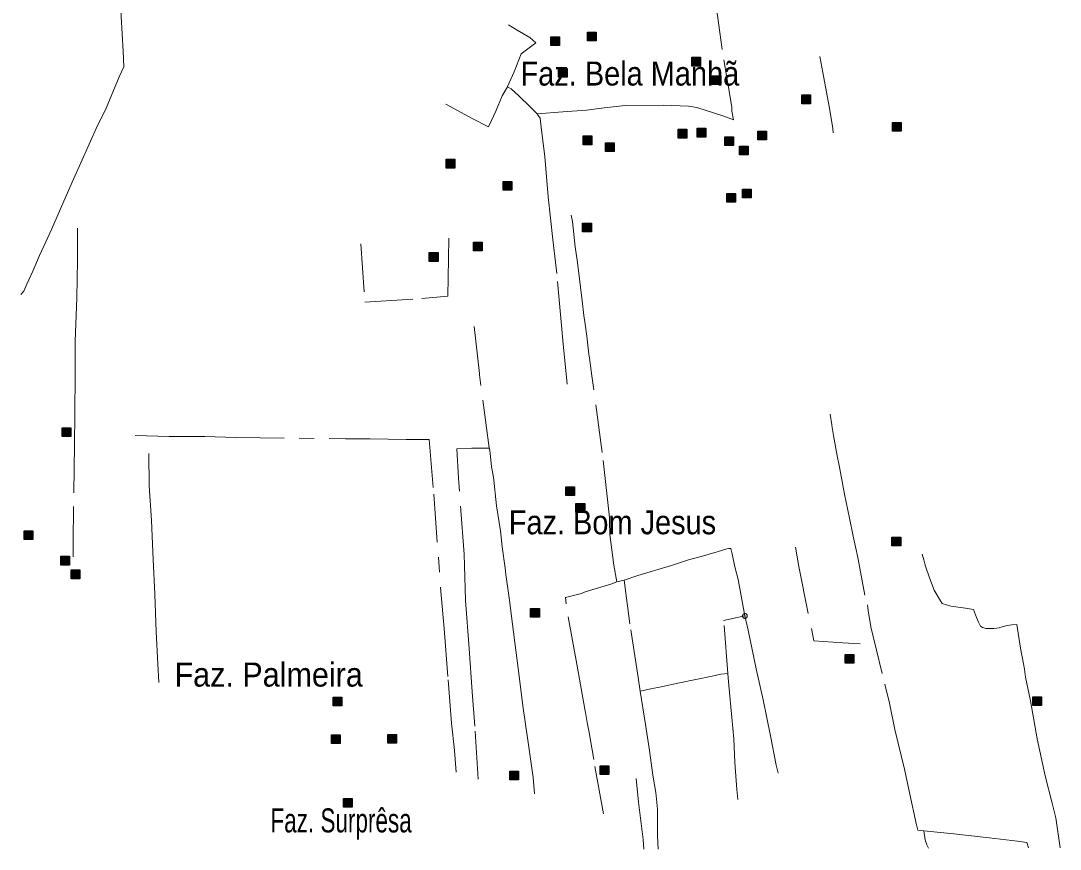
# Model space of a CAD drawing. Extents: x 393.5 to 446.9, y 8064.8 to 8120.4.
# Drawn here: x 425.04 to 431.96, y 8064.99 to 8070.5 of the extents above; entities that cross this region are included whole.
import ezdxf

# ---------------------------------------------------------------- set-up
doc = ezdxf.new("R2010")
doc.units = 0
doc.header["$LTSCALE"] = 0.064
doc.header["$PDMODE"] = 32
doc.header["$PDSIZE"] = 0.032
doc.linetypes.add('DOT_DASHED', pattern=[7.7, 5, -1.2, 0.3, -1.2])
doc.layers.add('2', color=7, linetype='Continuous', lineweight=25)
doc.layers.add('22', color=7, linetype='DOT_DASHED', lineweight=13)
doc.layers.add('61', color=7, linetype='Continuous')

msp = doc.modelspace()

# ---------------------------------------------------------------- hatches: boundary and pattern name
at = {"layer": '2'}
for points in [[(428.8142, 8070.4241), (428.8722, 8070.4241), (428.8722, 8070.3661), (428.8142, 8070.3661)], [(428.5692, 8070.3936), (428.6272, 8070.3936), (428.6272, 8070.3356), (428.5692, 8070.3356)], [(429.5083, 8070.2564), (429.5663, 8070.2564), (429.5663, 8070.1984), (429.5083, 8070.1984)], [(428.6204, 8070.1826), (428.6784, 8070.1826), (428.6784, 8070.1246), (428.6204, 8070.1246)], [(429.6434, 8070.1327), (429.7014, 8070.1327), (429.7014, 8070.0747), (429.6434, 8070.0747)], [(430.2406, 8070.0055), (430.2986, 8070.0055), (430.2986, 8069.9475), (430.2406, 8069.9475)], [(429.4184, 8069.7773), (429.4764, 8069.7773), (429.4764, 8069.7193), (429.4184, 8069.7193)], [(429.5447, 8069.7839), (429.6027, 8069.7839), (429.6027, 8069.7259), (429.5447, 8069.7259)], [(430.8448, 8069.8231), (430.9028, 8069.8231), (430.9028, 8069.7651), (430.8448, 8069.7651)], [(428.7855, 8069.7329), (428.8435, 8069.7329), (428.8435, 8069.6749), (428.7855, 8069.6749)], [(429.7275, 8069.7276), (429.7855, 8069.7276), (429.7855, 8069.6696), (429.7275, 8069.6696)], [(429.9478, 8069.7656), (430.0058, 8069.7656), (430.0058, 8069.7076), (429.9478, 8069.7076)], [(428.9337, 8069.6877), (428.9917, 8069.6877), (428.9917, 8069.6297), (428.9337, 8069.6297)], [(429.8257, 8069.6645), (429.8837, 8069.6645), (429.8837, 8069.6065), (429.8257, 8069.6065)], [(427.8739, 8069.5776), (427.9319, 8069.5776), (427.9319, 8069.5196), (427.8739, 8069.5196)], [(428.2525, 8069.4307), (428.3105, 8069.4307), (428.3105, 8069.3727), (428.2525, 8069.3727)], [(429.8467, 8069.3783), (429.9047, 8069.3783), (429.9047, 8069.3203), (429.8467, 8069.3203)], [(429.7413, 8069.3506), (429.7993, 8069.3506), (429.7993, 8069.2926), (429.7413, 8069.2926)], [(428.7819, 8069.1535), (428.8399, 8069.1535), (428.8399, 8069.0955), (428.7819, 8069.0955)], [(428.0554, 8069.0256), (428.1134, 8069.0256), (428.1134, 8068.9676), (428.0554, 8068.9676)], [(427.7611, 8068.9562), (427.8191, 8068.9562), (427.8191, 8068.8982), (427.7611, 8068.8982)], [(425.316, 8067.7913), (425.374, 8067.7913), (425.374, 8067.7333), (425.316, 8067.7333)], [(428.6705, 8067.3979), (428.7285, 8067.3979), (428.7285, 8067.3399), (428.6705, 8067.3399)], [(428.7375, 8067.2877), (428.7955, 8067.2877), (428.7955, 8067.2297), (428.7375, 8067.2297)], [(425.0637, 8067.1044), (425.1217, 8067.1044), (425.1217, 8067.0464), (425.0637, 8067.0464)], [(430.8409, 8067.0625), (430.8989, 8067.0625), (430.8989, 8067.0045), (430.8409, 8067.0045)], [(425.3087, 8066.9352), (425.3667, 8066.9352), (425.3667, 8066.8772), (425.3087, 8066.8772)], [(425.3765, 8066.8442), (425.4345, 8066.8442), (425.4345, 8066.7862), (425.3765, 8066.7862)], [(428.4356, 8066.5888), (428.4936, 8066.5888), (428.4936, 8066.5308), (428.4356, 8066.5308)], [(430.5301, 8066.2821), (430.5881, 8066.2821), (430.5881, 8066.2241), (430.5301, 8066.2241)], [(427.1208, 8065.9976), (427.1788, 8065.9976), (427.1788, 8065.9396), (427.1208, 8065.9396)], [(431.7794, 8065.9995), (431.8374, 8065.9995), (431.8374, 8065.9415), (431.7794, 8065.9415)], [(427.1091, 8065.7477), (427.1671, 8065.7477), (427.1671, 8065.6897), (427.1091, 8065.6897)], [(427.4838, 8065.7504), (427.5418, 8065.7504), (427.5418, 8065.6924), (427.4838, 8065.6924)], [(428.2961, 8065.5062), (428.3541, 8065.5062), (428.3541, 8065.4482), (428.2961, 8065.4482)], [(428.899, 8065.5413), (428.957, 8065.5413), (428.957, 8065.4833), (428.899, 8065.4833)], [(427.1903, 8065.3233), (427.2483, 8065.3233), (427.2483, 8065.2653), (427.1903, 8065.2653)]]:
    msp.add_hatch(color=256, dxfattribs=at).paths.add_polyline_path(points)

# ---------------------------------------------------------------- linework, layer by layer
for points in [[(428.8142, 8070.4241), (428.8722, 8070.4241), (428.8722, 8070.3661), (428.8142, 8070.3661)], [(428.5692, 8070.3936), (428.6272, 8070.3936), (428.6272, 8070.3356), (428.5692, 8070.3356)], [(429.5083, 8070.2564), (429.5663, 8070.2564), (429.5663, 8070.1984), (429.5083, 8070.1984)], [(428.6204, 8070.1826), (428.6784, 8070.1826), (428.6784, 8070.1246), (428.6204, 8070.1246)], [(429.6434, 8070.1327), (429.7014, 8070.1327), (429.7014, 8070.0747), (429.6434, 8070.0747)], [(430.2406, 8070.0055), (430.2986, 8070.0055), (430.2986, 8069.9475), (430.2406, 8069.9475)], [(429.4184, 8069.7773), (429.4764, 8069.7773), (429.4764, 8069.7193), (429.4184, 8069.7193)], [(429.5447, 8069.7839), (429.6027, 8069.7839), (429.6027, 8069.7259), (429.5447, 8069.7259)], [(430.8448, 8069.8231), (430.9028, 8069.8231), (430.9028, 8069.7651), (430.8448, 8069.7651)], [(428.7855, 8069.7329), (428.8435, 8069.7329), (428.8435, 8069.6749), (428.7855, 8069.6749)], [(429.7275, 8069.7276), (429.7855, 8069.7276), (429.7855, 8069.6696), (429.7275, 8069.6696)], [(429.9478, 8069.7656), (430.0058, 8069.7656), (430.0058, 8069.7076), (429.9478, 8069.7076)], [(428.9337, 8069.6877), (428.9917, 8069.6877), (428.9917, 8069.6297), (428.9337, 8069.6297)], [(429.8257, 8069.6645), (429.8837, 8069.6645), (429.8837, 8069.6065), (429.8257, 8069.6065)], [(427.8739, 8069.5776), (427.9319, 8069.5776), (427.9319, 8069.5196), (427.8739, 8069.5196)], [(428.2525, 8069.4307), (428.3105, 8069.4307), (428.3105, 8069.3727), (428.2525, 8069.3727)], [(429.8467, 8069.3783), (429.9047, 8069.3783), (429.9047, 8069.3203), (429.8467, 8069.3203)], [(429.7413, 8069.3506), (429.7993, 8069.3506), (429.7993, 8069.2926), (429.7413, 8069.2926)], [(428.7819, 8069.1535), (428.8399, 8069.1535), (428.8399, 8069.0955), (428.7819, 8069.0955)], [(428.0554, 8069.0256), (428.1134, 8069.0256), (428.1134, 8068.9676), (428.0554, 8068.9676)], [(427.7611, 8068.9562), (427.8191, 8068.9562), (427.8191, 8068.8982), (427.7611, 8068.8982)], [(425.316, 8067.7913), (425.374, 8067.7913), (425.374, 8067.7333), (425.316, 8067.7333)], [(428.6705, 8067.3979), (428.7285, 8067.3979), (428.7285, 8067.3399), (428.6705, 8067.3399)], [(428.7375, 8067.2877), (428.7955, 8067.2877), (428.7955, 8067.2297), (428.7375, 8067.2297)], [(425.0637, 8067.1044), (425.1217, 8067.1044), (425.1217, 8067.0464), (425.0637, 8067.0464)], [(430.8409, 8067.0625), (430.8989, 8067.0625), (430.8989, 8067.0045), (430.8409, 8067.0045)], [(425.3087, 8066.9352), (425.3667, 8066.9352), (425.3667, 8066.8772), (425.3087, 8066.8772)], [(425.3765, 8066.8442), (425.4345, 8066.8442), (425.4345, 8066.7862), (425.3765, 8066.7862)], [(428.4356, 8066.5888), (428.4936, 8066.5888), (428.4936, 8066.5308), (428.4356, 8066.5308)], [(430.5301, 8066.2821), (430.5881, 8066.2821), (430.5881, 8066.2241), (430.5301, 8066.2241)], [(427.1208, 8065.9976), (427.1788, 8065.9976), (427.1788, 8065.9396), (427.1208, 8065.9396)], [(431.7794, 8065.9995), (431.8374, 8065.9995), (431.8374, 8065.9415), (431.7794, 8065.9415)], [(427.1091, 8065.7477), (427.1671, 8065.7477), (427.1671, 8065.6897), (427.1091, 8065.6897)], [(427.4838, 8065.7504), (427.5418, 8065.7504), (427.5418, 8065.6924), (427.4838, 8065.6924)], [(428.2961, 8065.5062), (428.3541, 8065.5062), (428.3541, 8065.4482), (428.2961, 8065.4482)], [(428.899, 8065.5413), (428.957, 8065.5413), (428.957, 8065.4833), (428.899, 8065.4833)], [(427.1903, 8065.3233), (427.2483, 8065.3233), (427.2483, 8065.2653), (427.1903, 8065.2653)]]:
    msp.add_lwpolyline(points, close=True, dxfattribs=at)
at = {"layer": '22'}
msp.add_line((428.281, 8070.0604), (428.2821, 8070.0628), dxfattribs=at)
for points in [[(429.7755, 8069.9239), (429.7112, 8070.3075), (429.6798, 8070.5338), (429.6553, 8070.6679), (429.6408, 8070.7538), (429.6116, 8070.947), (429.5918, 8071.0786), (429.5603, 8071.2467), (429.527, 8071.5031), (429.5113, 8071.571), (429.4842, 8071.7687), (429.4316, 8072.0871), (429.4123, 8072.2022), (429.4107, 8072.2302), (429.4066, 8072.2667), (429.4051, 8072.2824)], [(425.0414, 8068.6771), (425.0626, 8068.701), (425.0826, 8068.7458), (425.1208, 8068.8335), (425.1669, 8068.9367), (425.2091, 8069.0283), (425.2452, 8069.1101), (425.3426, 8069.335), (425.3928, 8069.446), (425.4409, 8069.5551), (425.5524, 8069.8034), (425.6046, 8069.9066), (425.6959, 8070.1257), (425.728, 8070.1939), (425.722, 8070.2971), (425.7089, 8070.5279), (425.7009, 8070.7012), (425.6778, 8071.0548), (425.6607, 8071.482), (425.6538, 8071.6448)], [(428.2821, 8070.0628), (428.3256, 8070.1597), (428.3734, 8070.28), (428.4702, 8070.3529), (428.4297, 8070.3884), (428.3469, 8070.437), (428.2891, 8070.4726)], [(430.3602, 8070.261), (430.3866, 8070.1202), (430.4224, 8069.9281), (430.4394, 8069.8385), (430.4469, 8069.7819), (430.4488, 8069.7526)], [(428.281, 8070.0604), (428.2467, 8069.9995), (428.2043, 8069.8985), (428.1542, 8069.7938), (428.0463, 8069.848), (427.8709, 8069.9434)], [(428.4792, 8069.8796), (428.432, 8069.9271), (428.358, 8070), (428.306, 8070.0468), (428.281, 8070.0604)], [(428.4792, 8069.8796), (428.6507, 8069.8931), (428.8081, 8069.905), (428.9253, 8069.9203), (429.0655, 8069.9356), (429.3192, 8069.9373), (429.4872, 8069.9322), (429.5414, 8069.922), (429.7146, 8069.866), (429.7863, 8069.8405), (429.7758, 8069.8983), (429.7755, 8069.9239)], [(428.6438, 8068.4466), (428.6101, 8068.817), (428.5842, 8069.0447), (428.552, 8069.3279), (428.5306, 8069.5963), (428.5089, 8069.7709), (428.4984, 8069.8507), (428.4813, 8069.8765), (428.4792, 8069.8796)], [(428.7955, 8068.4962), (428.7903, 8068.5385), (428.7787, 8068.6357), (428.7479, 8068.891), (428.7325, 8068.9957), (428.7132, 8069.1639), (428.7055, 8069.2051)], [(425.4195, 8069.1183), (425.4181, 8068.9036), (425.4136, 8068.6564), (425.4028, 8068.3656), (425.4043, 8068.1489), (425.4009, 8067.8797), (425.3986, 8067.6786), (425.3929, 8067.2666), (425.3906, 8067.028), (425.3906, 8066.9307)], [(427.306, 8069.0148), (427.3321, 8068.6263), (427.7117, 8068.6516), (427.8841, 8068.6657), (427.8885, 8068.9145), (427.8914, 8069.0537)], [(428.0957, 8068.1428), (428.0946, 8068.1512), (428.0604, 8068.4653)], [(428.824, 8068.2805), (428.8098, 8068.4008), (428.7955, 8068.4962)], [(428.6785, 8068.0804), (428.6499, 8068.3725), (428.6438, 8068.4466)], [(428.9601, 8067.1945), (428.9542, 8067.2539), (428.9125, 8067.627), (428.8425, 8068.1373), (428.8271, 8068.2532), (428.824, 8068.2805)], [(428.1604, 8067.6565), (428.1, 8068.1065), (428.0957, 8068.1428)], [(430.6609, 8066.6772), (430.6129, 8066.9264), (430.5834, 8067.0683), (430.5583, 8067.1894), (430.5243, 8067.3499), (430.4919, 8067.5296), (430.4757, 8067.6041), (430.4521, 8067.7403), (430.4432, 8067.7919), (430.4415, 8067.8105), (430.429, 8067.8821)], [(425.8021, 8067.7401), (426.0287, 8067.733), (426.2676, 8067.733), (426.4745, 8067.7258), (427.2027, 8067.7177), (427.3677, 8067.7177), (427.6066, 8067.7121)], [(427.6066, 8067.7121), (427.714, 8067.7121), (427.7608, 8067.7121), (427.7904, 8067.3489), (427.8384, 8066.7), (427.8594, 8066.4551), (427.8866, 8066.1133), (427.9087, 8065.8242), (427.9284, 8065.6425), (427.9406, 8065.4996)], [(428.0854, 8065.4518), (428.063, 8065.8055), (428.0466, 8066.0341), (428.0256, 8066.321), (428.0012, 8066.6441), (427.9942, 8066.8733), (427.9922, 8066.9493), (427.9558, 8067.456), (427.9453, 8067.6495), (428.045, 8067.6546), (428.1605, 8067.656)], [(428.1608, 8067.6538), (428.1605, 8067.656), (428.1604, 8067.6565)], [(428.2347, 8067.104), (428.2086, 8067.2708), (428.1874, 8067.4623), (428.1752, 8067.5302), (428.1652, 8067.6227), (428.1608, 8067.6538)], [(425.8932, 8067.6199), (425.8971, 8067.4049), (425.9107, 8067.1728), (425.9217, 8066.9145), (425.9327, 8066.6825), (425.9437, 8066.4317), (425.9547, 8066.2198), (425.9605, 8066.0947)], [(429.0095, 8066.7662), (428.9898, 8066.8767), (428.9637, 8067.0812), (428.9597, 8067.1669), (428.9601, 8067.1945)], [(428.271, 8066.8145), (428.2652, 8066.8564), (428.246, 8066.999), (428.239, 8067.0635), (428.2347, 8067.104)], [(429.8618, 8066.5381), (429.8618, 8066.5383), (429.8164, 8066.7802), (429.7943, 8066.8661), (429.777, 8066.9508), (429.7692, 8066.9881), (429.7559, 8066.9881), (429.7424, 8066.9845), (429.6776, 8066.9651), (429.5698, 8066.9336), (429.4856, 8066.9107), (429.3742, 8066.8735), (429.1483, 8066.8075), (429.0582, 8066.776)], [(430.1989, 8066.9953), (430.22, 8066.8671), (430.3213, 8066.372), (430.5147, 8066.3591), (430.6284, 8066.3519)], [(431.639, 8066.4791), (431.6078, 8066.4757), (431.56, 8066.4609), (431.5551, 8066.4596), (431.5192, 8066.4546), (431.4946, 8066.4546), (431.4684, 8066.4546), (431.4439, 8066.4611), (431.4307, 8066.4709), (431.416, 8066.4969), (431.4028, 8066.5279), (431.3845, 8066.5811), (431.3305, 8066.5908), (431.2338, 8066.6037), (431.1749, 8066.6216), (431.1651, 8066.6395), (431.1213, 8066.7099), (431.0902, 8066.7923), (431.0647, 8066.8706), (431.0605, 8066.8857), (431.0536, 8066.9123), (431.0421, 8066.9501)], [(428.4605, 8065.3542), (428.4524, 8065.4633), (428.4191, 8065.6959), (428.3841, 8065.9404), (428.3571, 8066.1552), (428.3213, 8066.4295), (428.2924, 8066.6591), (428.271, 8066.8145)], [(428.7988, 8066.6996), (428.8198, 8066.7063), (428.9696, 8066.7488), (429.0095, 8066.7662)], [(429.0095, 8066.7662), (429.0573, 8066.7758), (429.0582, 8066.776)], [(429.1655, 8066.038), (429.1508, 8066.1293), (429.097, 8066.4854), (429.0582, 8066.776)], [(428.801, 8065.8962), (428.7974, 8065.919), (428.7426, 8066.2166), (428.671, 8066.6179), (428.6677, 8066.661), (428.7747, 8066.6882), (428.7988, 8066.6996)], [(430.6787, 8066.6132), (430.6831, 8066.5745), (430.7008, 8066.4656)], [(429.7486, 8066.1559), (429.7205, 8066.5074), (429.8099, 8066.5283), (429.8618, 8066.5381)], [(430.0835, 8065.4918), (430.0701, 8065.5447), (430.0317, 8065.741), (429.9837, 8065.9797), (429.9371, 8066.1868), (429.8832, 8066.444), (429.8618, 8066.5381)], [(430.7008, 8066.4656), (430.7925, 8066.0843), (430.825, 8065.9582), (430.8604, 8065.7833), (430.9246, 8065.5175), (430.9593, 8065.352), (431.0013, 8065.1579), (431.0124, 8065.1121), (431.0523, 8065.1092)], [(431.723, 8066.1834), (431.7161, 8066.2186), (431.6969, 8066.3246), (431.6714, 8066.4825), (431.639, 8066.4791)], [(431.961, 8064.9955), (431.9327, 8065.1957), (431.9084, 8065.2918), (431.8599, 8065.4743), (431.8074, 8065.72), (431.763, 8065.9731), (431.7306, 8066.13), (431.723, 8066.1834)], [(429.1655, 8066.038), (429.2347, 8066.0523), (429.3055, 8066.0667), (429.4256, 8066.0923), (429.6446, 8066.137), (429.7019, 8066.1513), (429.748, 8066.1558), (429.7486, 8066.1559)], [(429.8141, 8065.3173), (429.8085, 8065.3841), (429.7941, 8065.5631), (429.7884, 8065.7197), (429.7624, 8066.0035), (429.7537, 8066.1), (429.7486, 8066.1559)], [(429.2846, 8064.9863), (429.2806, 8065.0727), (429.2806, 8065.2519), (429.2685, 8065.3629), (429.2485, 8065.4778), (429.2264, 8065.6433), (429.2, 8065.8154), (429.1655, 8066.038)], [(428.9214, 8065.2207), (428.8552, 8065.5827), (428.8251, 8065.7618), (428.8111, 8065.83), (428.801, 8065.8962)], [(429.1883, 8064.9859), (429.1842, 8065.0494), (429.1541, 8065.2986), (429.1381, 8065.4563)], [(431.0836, 8064.9926), (431.0732, 8065.014), (431.0629, 8065.0484), (431.0526, 8065.1074), (431.0523, 8065.1092)], [(431.75, 8064.9948), (431.7382, 8065.0305), (431.6762, 8065.0405), (431.4871, 8065.0606), (431.3498, 8065.0763), (431.2523, 8065.0878), (431.0523, 8065.1092)]]:
    msp.add_lwpolyline(points, dxfattribs=at)
msp.add_point((429.8618, 8066.5382), dxfattribs=at)

# ---------------------------------------------------------------- texts
at = {"layer": '61'}
for s, width, p in [('Faz. Bela Manhã', 0.9, (428.3684, 8070.0684)), ('Faz. Bom Jesus', 0.9, (428.29, 8067.0819)), ('Faz. Palmeira', 0.95, (426.0646, 8066.0682)), ('Faz. Surprêsa', 0.7, (426.7033, 8065.0976))]:
    msp.add_text(s, height=0.16, dxfattribs=dict(at, width=width)).set_placement(p)

doc.saveas('drawing.dxf')
